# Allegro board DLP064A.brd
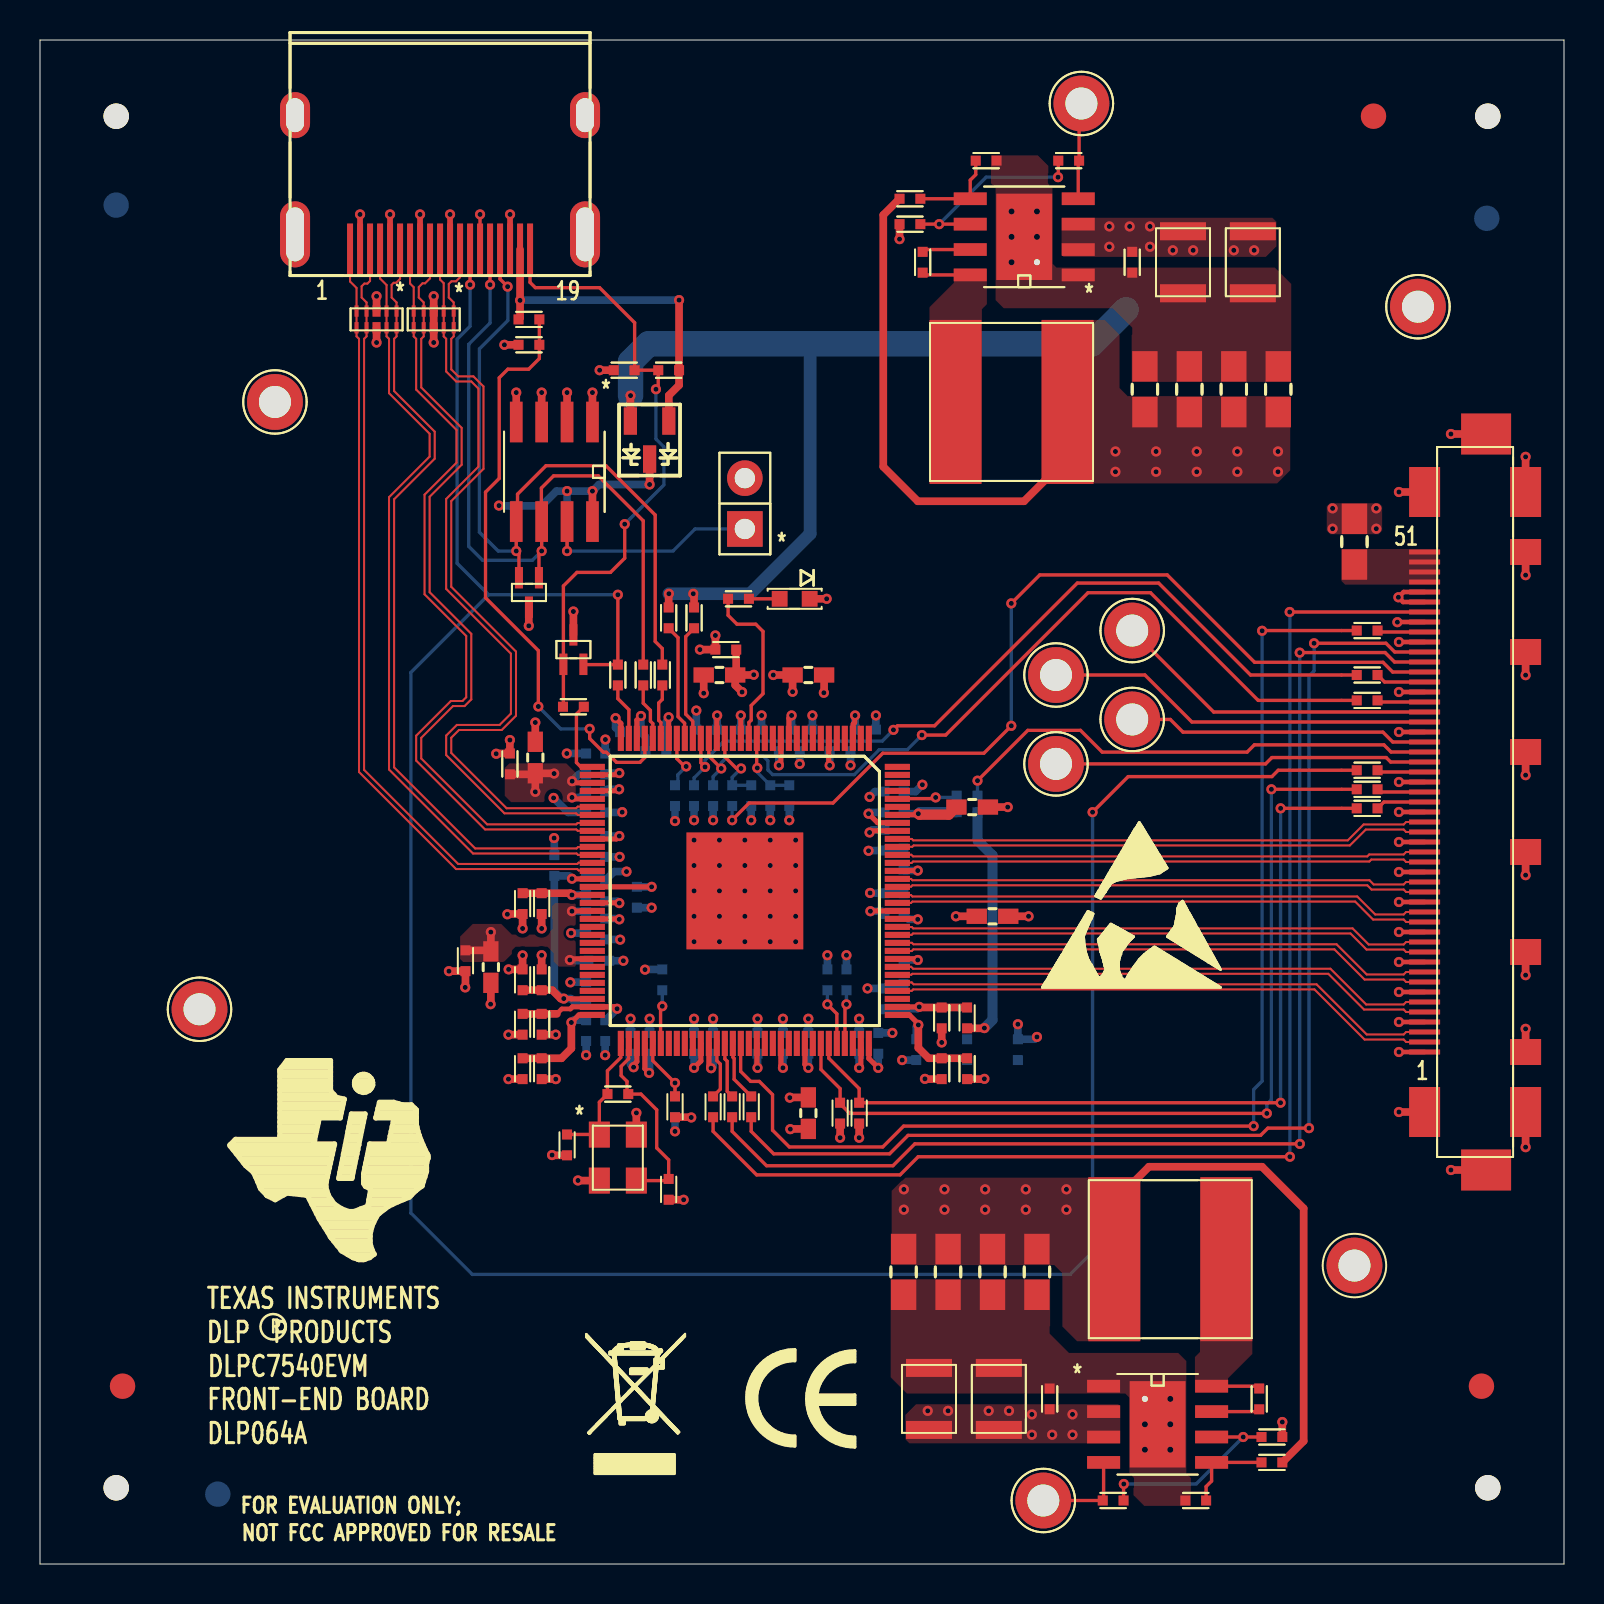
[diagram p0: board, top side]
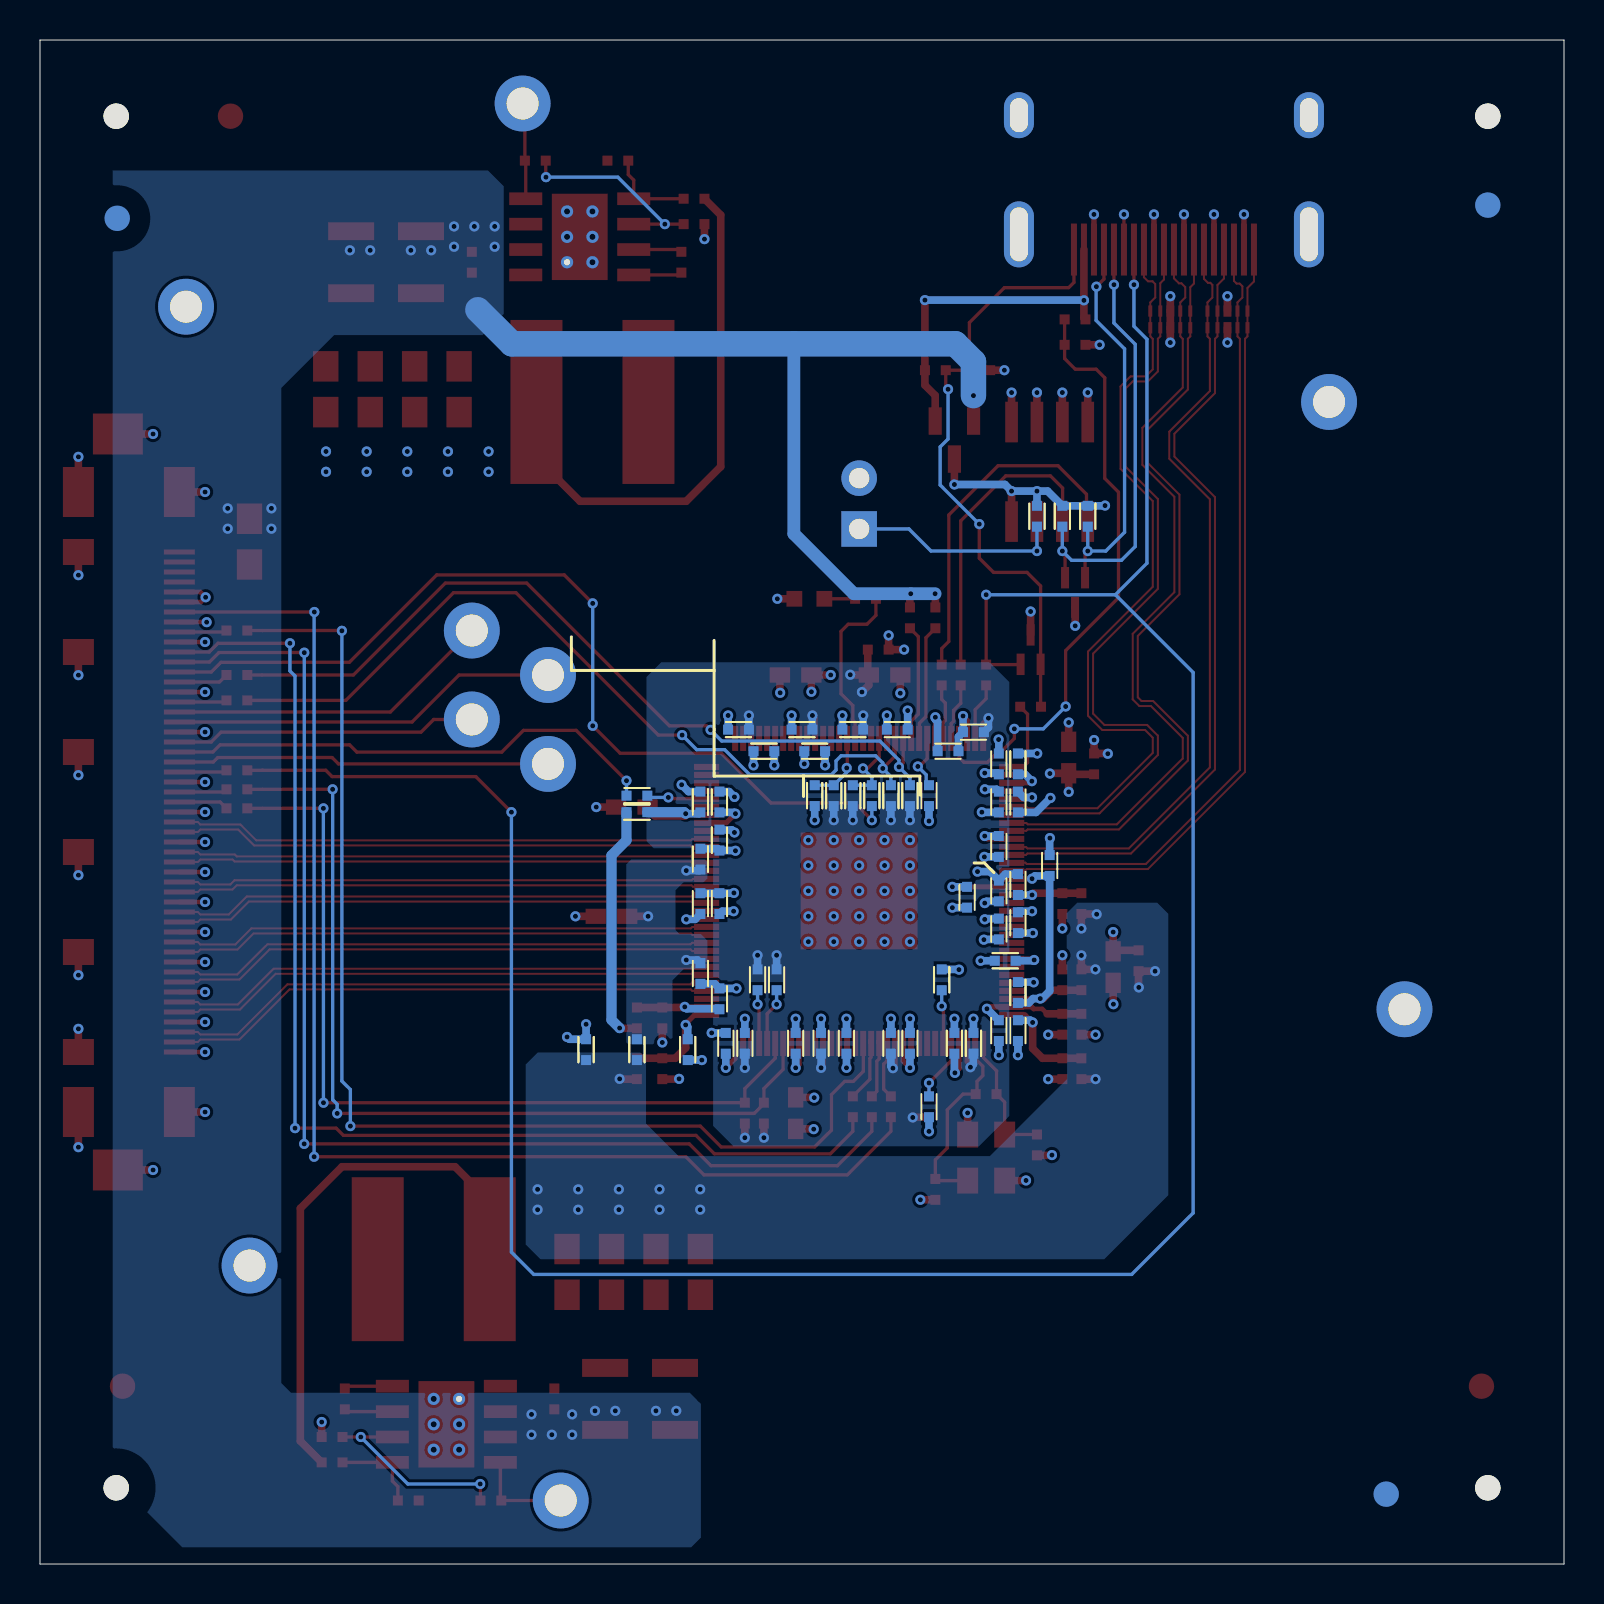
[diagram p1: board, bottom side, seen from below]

Outline 76.2 x 76.2 mm; copper layers: TOP, LY2, LY3, BOTTOM. Coordinates in mm from the lower left corner of the outline.
Outline path: 0,76.2 0,0 76.2,0 76.2,76.2 0,76.2

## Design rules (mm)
constraint set DEFAULT: min track width 0.165
net group TX: nets TX0N TX0P TX1N TX1P TX2N TX2P TX3N TX3P TX4N TX4P TX5N TX5P TX6N TX6P TX7N TX7P

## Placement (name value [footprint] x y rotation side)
C1  1uF  [0402]  43.5 66.99 180 top
C2  100nF  [0402]  44.13 65.09 90 top
C3  100pF  [0402]  54.61 65.09 90 top
C4  10uF  [1210]  57.15 65.09 270 top
C5  10uF  [1210]  60.64 65.09 270 top
C6  22uF  [0805]  55.24 58.74 270 top
C7  22uF  [0805]  57.47 58.74 270 top
C8  22uF  [0805]  59.69 58.74 270 top
C9  22uF  [0805]  61.91 58.74 270 top
C10  10uF  [0603]  24.77 40.32 90 top
C11  10uF  [0603]  33.97 44.45 180 top
C12  10uF  [0603]  38.42 44.45 0 top
C13  10uF  [0603]  22.54 29.84 270 top
C14  4.7uF  [0402]  25.08 33.02 270 top
C15  10uF  [0603]  47.62 32.38 0 top
C16  4.7uF  [0402]  25.08 29.21 90 top
C17  1uF  [0402]  25.08 26.99 270 top
C18  1uF  [0402]  25.08 24.77 270 top
C19  10uF  [0603]  38.42 22.54 270 top
C20  4.7uF  [0402]  45.09 27.3 270 top
C21  4.7uF  [0402]  45.09 24.77 270 top
C22  18pF  [0402]  26.35 20.95 90 top
C23  18pF  [0402]  31.43 18.73 90 top
C24  22uF  [0805]  43.18 14.61 90 top
C25  22uF  [0805]  45.4 14.61 90 top
C26  22uF  [0805]  47.62 14.61 90 top
C27  22uF  [0805]  49.85 14.61 90 top
C28  10uF  [1210]  44.45 8.26 90 top
C29  10uF  [1210]  47.94 8.26 90 top
C30  100pF  [0402]  50.48 8.26 270 top
C31  100nF  [0402]  60.96 8.26 270 top
C32  1uF  [0402]  61.59 6.35 0 top
C33  100nF  [0402]  42.23 38.1 90 bottom
C34  100nF  [0402]  43.18 38.1 90 bottom
C35  100nF  [0402]  41.27 41.72 0 bottom
C36  100nF  [0402]  40.01 40.64 0 bottom
C37  100nF  [0402]  38.1 41.72 0 bottom
C38  100nF  [0402]  37.47 40.64 0 bottom
C39  1uF  [0402]  37.47 38.42 90 bottom
C40  100nF  [0402]  35.56 41.72 0 bottom
C41  100nF  [0402]  33.34 41.72 180 bottom
C42  100nF  [0402]  30.8 40.64 180 bottom
C43  100nF  [0402]  29.53 41.59 0 bottom
C44  100nF  [0402]  28.26 40.01 90 bottom
C45  100nF  [0402]  28.26 38.1 270 bottom
C46  100nF  [0402]  27.3 40.01 90 bottom
C47  100nF  [0402]  27.3 38.1 270 bottom
C48  100nF  [0402]  43.18 35.24 90 bottom
C49  100nF  [0402]  43.18 33.02 90 bottom
C50  100nF  [0402]  42.23 36.2 270 bottom
C51  100nF  [0402]  42.23 33.02 90 bottom
C52  100nF  [0402]  29.84 33.34 270 bottom
C53  100nF  [0402]  28.26 35.88 270 bottom
C54  100nF  [0402]  28.26 33.66 90 bottom
C55  100nF  [0402]  28.26 31.75 270 bottom
C56  100nF  [0402]  27.3 33.97 90 bottom
C57  100nF  [0402]  27.3 32.07 270 bottom
C58  100nF  [0402]  25.72 34.92 90 bottom
C59  100nF  [0402]  43.18 29.53 270 bottom
C60  100nF  [0402]  42.23 28.26 90 bottom
C61  100nF  [0402]  28.26 26.67 270 bottom
C62  100nF  [0402]  27.94 30.16 0 bottom
C63  100nF  [0402]  27.3 28.57 90 bottom
C64  100nF  [0402]  27.3 26.67 270 bottom
C65  100nF  [0402]  43.81 25.72 270 bottom
C66  100nF  [0402]  41.91 26.04 90 bottom
C67  100nF  [0402]  40.96 26.04 90 bottom
C68  100nF  [0402]  38.42 26.04 90 bottom
C69  100nF  [0402]  37.15 26.04 90 bottom
C70  100nF  [0402]  35.88 26.04 90 bottom
C71  100nF  [0402]  33.66 26.04 90 bottom
C72  100nF  [0402]  32.7 26.04 90 bottom
C73  100nF  [0402]  30.48 26.04 90 bottom
C74  100nF  [0402]  29.53 26.04 90 bottom
C75  10uF  [0603]  46.61 37.85 0 top
D1  BAT54CFILM  [SOT-23-BAT54S_ST]  30.48 56.2 180 top
D2  RCLAMP0502BATCT  [SEMTECH_SC-75_SOT523]  24.45 48.58 0 top
D3  RCLAMP0502BATCT  [SEMTECH_SC-75_SOT523]  26.67 45.72 180 top
D4  blue  [LED-LTST-C190_LITEON]  37.78 48.26 180 top
J1  2086581001  [MOLEX_47151-0001]  20 65.72 180 top
J2  HDR,2P,1R  [HDR2P_1R]  35.24 51.75 0 top
J3  FI-RE51S-VF-R1300  [FI-R51-HF_VF_DUAL]  71.75 38.1 90 top
L1  6.8uH  [BOURNS_SRN8040]  48.58 58.1 180 top
L2  BLM15PX121SN1D  [0402]  34.29 45.72 180 top
L3  BLM15PX121SN1D  [0402]  23.5 40.01 270 top
L4  BLM15PX121SN1D  [0402]  21.27 30.16 90 top
L5  BLM15PX121SN1D  [0402]  24.13 33.02 90 top
L6  BLM15PX121SN1D  [0402]  24.13 29.21 270 top
L7  BLM15PX121SN1D  [0402]  24.13 26.99 90 top
L8  BLM15PX121SN1D  [0402]  24.13 24.77 90 top
L9  BLM15PX121SN1D  [0402]  46.35 27.3 270 top
L10  BLM15PX121SN1D  [0402]  46.35 24.77 270 top
L11  3.6uH  [BOURNS_SRN8040]  56.52 15.24 0 top
L12  BLM15PX121SN1D  [0402]  48.9 25.72 90 bottom
L13  BLM15PX121SN1D  [0402]  46.35 25.72 270 bottom
L14  BLM15PX121SN1D  [0402]  46.35 37.59 0 bottom
NOREF  -  []  -19.94 -62.8 0 top
NOREF#2  -  []  -68.53 58.93 0 top
NOREF#3  -  []  0 76.2 0 top
NOREF#4  -  []  -10.16 -10.16 0 top
NOREF#5  -  [unnamed#2]  72.39 3.81 90 top
NOREF#6  -  [unnamed#2]  66.67 72.39 90 top
NOREF#7  -  []  0 0 0 top
NOREF#8  -  []  -10.16 86.36 0 top
NOREF#9  -  []  -50.44 43.56 0 top
NOREF#10  -  []  -88.27 72.95 0 top
NOREF#11  -  [unnamed#2]  3.81 3.81 90 top
NOREF#12  -  []  240.78 -103.99 0 top
NOREF#13  -  []  -67.57 -40.82 0 top
NOREF#14  -  []  86.36 86.36 0 top
NOREF#15  -  []  21.03 2.51 0 top
NOREF#16  -  []  0 0 90 top
NOREF#17  -  [unnamed#2]  72.07 8.89 90 top
NOREF#18  -  []  0 0 90 top
NOREF#19  -  [unnamed#2]  3.81 72.39 90 top
NOREF#20  -  [unnamed#2]  4.13 8.89 90 top
NOREF#21  -  [unnamed#2]  72.39 72.39 90 top
NOREF#22  -  []  -25.35 67.44 0 top
NOREF#23  -  [unnamed#2]  8.89 3.49 90 bottom
NOREF#24  -  [unnamed#2]  72.34 67.28 90 bottom
NOREF#25  -  [unnamed#2]  3.81 67.94 90 bottom
R1  100k  [0402]  43.5 68.26 180 top
R2  43.2K  [0402]  47.31 70.17 180 top
R3  100k  [0402]  51.44 70.17 0 top
R4  1.5k  [0402]  24.45 62.23 180 top
R5  3k  [0402]  24.45 60.96 0 top
R6  100k  [0402]  29.21 59.69 0 top
R7  100k  [0402]  31.43 59.69 180 top
R8  10k  [0402]  31.43 47.31 270 top
R9  10k  [0402]  32.7 47.31 270 top
R10  300  [0402]  34.92 48.26 180 top
R11  0  [0805]  65.72 51.12 90 top
R12  22  [0402]  66.36 46.67 180 top
R13  22  [0402]  26.67 42.86 180 top
R14  0  [0402]  28.89 44.45 90 top
R15  22  [0402]  30.16 44.45 90 top
R16  22  [0402]  31.11 44.45 90 top
R17  22  [0402]  66.36 44.45 180 top
R18  22  [0402]  66.36 43.18 180 top
R19  22  [0402]  66.36 39.69 180 top
R20  22  [0402]  66.36 38.73 180 top
R21  22  [0402]  66.36 37.78 180 top
R22  1M  [0402]  28.89 23.5 180 top
R23  10k  [0402]  31.75 22.86 90 top
R24  22  [0402]  33.66 22.86 90 top
R25  22  [0402]  34.61 22.86 90 top
R26  22  [0402]  35.56 22.86 90 top
R27  10k  [0402]  40.01 22.54 90 top
R28  10k  [0402]  40.96 22.54 90 top
R29  100k  [0402]  53.66 3.17 180 top
R30  43.2K  [0402]  57.78 3.17 0 top
R31  0  [0402]  61.59 5.08 0 top
R32  10k  [0402]  26.35 52.39 270 bottom
R33  10k  [0402]  25.08 52.39 270 bottom
R34  10k  [0402]  23.81 52.39 270 bottom
R35  22  [0402]  46.35 38.42 180 bottom
R36  22k  [0402]  36.51 38.42 90 bottom
R37  10k  [0402]  35.56 38.42 90 bottom
R38  22  [0402]  34.61 38.42 90 bottom
R39  10k  [0402]  33.66 38.42 90 bottom
R40  10k  [0402]  32.7 38.42 90 bottom
R41  3k  [0402]  31.75 38.42 270 bottom
R42  10k  [0402]  40.32 29.21 270 bottom
R43  10k  [0402]  39.37 29.21 270 bottom
R44  1k  [0402]  31.11 29.21 270 bottom
R45  10k  [0402]  31.75 22.86 90 bottom
TP1  TP_WHT  [TP_KEYSTONE_5011]  52.07 73.03 180 top
TP2  TP_BLK  [TP_KEYSTONE_5011]  68.9 62.87 0 top
TP3  TP_BLK  [TP_KEYSTONE_5011]  11.75 58.1 0 top
TP4  TP_WHT  [TP_KEYSTONE_5011]  54.61 46.67 0 top
TP5  TP_WHT  [TP_KEYSTONE_5011]  50.8 44.45 0 top
TP6  TP_WHT  [TP_KEYSTONE_5011]  50.8 40.01 0 top
TP7  TP_WHT  [TP_KEYSTONE_5011]  54.61 42.23 0 top
TP8  TP_BLK  [TP_KEYSTONE_5011]  65.72 14.92 0 top
TP9  TP_BLK  [TP_KEYSTONE_5011]  7.98 27.74 0 top
TP10  TP_WHT  [TP_KEYSTONE_5011]  50.16 3.17 0 top
U1  TPD4E05U06DQAR  [TPD4E05U06DQAR_USON10]  16.83 62.23 270 top
U2  TPD4E05U06DQAR  [TPD4E05U06DQAR_USON10]  19.68 62.23 270 top
U3  LMR33620ADDAR  [HSOIC8_DDA0008J]  49.21 66.36 90 top
U4  M24C02-WMN6TP  [SOIC-8_3P90MM_WIDE]  25.72 54.61 180 top
U5  ITE6807  [ITE6807_LQFP128]  35.24 33.66 180 top
U6  LMR33620ADDAR  [HSOIC8_DDA0008J]  55.88 6.99 270 top
Y1  27.000MHz  [ABRACON_ABM8]  28.89 20.32 270 top

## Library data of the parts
C1-C3 C14 C16-C18 C20-C23 C30-C74 = PAS,CAP,NP: alternate symbols: (0402_1mm)
C4-C13 C15 C19 C24-C29 C75 = PAS,CAP,NP
D1 = PAS,DIODE,SCHOTTKY,BAT54CFILM
D2 D3 = PAS,DIODE,TVS,RClamp502b,small
D4 = PAS,DIODE,LED,ALT
J1 = EM,CONN,HDMI,1R,x1
J2 = EM,JMP,2P,1R
J3 = TMP_094452
L1 L11 = PAS,INDUCTOR, large
L2-L10 L12-L14 = PAS,INDUCTOR: alternate symbols: (0402_1mm)
R1-R10 R12-R45 = PAS,R,large: alternate symbols: (0402_1mm)
R11 = PAS,R,large
TP1 TP10 = Testpoint
TP2-TP9 = EM,TERM,TESTPOINT
U1 U2 = PAS,DIODE,ARRAY,TVS,TPD4E05U06
U3 U6 = PWR,REG,LMR33630,HSOIC8,1x
U4 = MEM,EEPROM,24LCxx
U5 = INF,VIDEO,IT6807_LQFP-128_0
Y1 = PAS,CRYSTAL,ABM11

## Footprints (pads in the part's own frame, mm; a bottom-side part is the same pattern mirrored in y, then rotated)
0402
  rect 0.5x0.5 smd: 1(-0.521,0) 2(0.521,0)
0603
  rect 1.016x0.762 smd: 1(-0.787,0) 2(0.787,0)
0805
  rect 1.524x1.27 smd: 1(-1.143,0) 2(1.143,0)
1210
  rect 0.9x2.3 smd: 1(-1.55,0) 2(1.55,0)
ABRACON_ABM8
  rect 1.3x1.05 smd: 1(-1.15,-0.925) 2(1.15,-0.925) 3(1.15,0.925) 4(-1.15,0.925)
BOURNS_SRN8040
  rect 2.6x8.2 smd: 1(-2.8,0) 2(2.8,0)
FI-R51-HF_VF_DUAL
  rect 0.25x1.55 smd: 1(-12.5,2.525) 2(-12,2.525) 3(-11.5,2.525) 4(-11,2.525) 5(-10.5,2.525) 6(-10,2.525) 7(-9.5,2.525) 8(-9,2.525) 9(-8.5,2.525) 10(-8,2.525) 11(-7.5,2.525) 12(-7,2.525) 13(-6.5,2.525) 14(-6,2.525) 15(-5.5,2.525) 16(-5,2.525) 17(-4.5,2.525) 18(-4,2.525) 19(-3.5,2.525) 20(-3,2.525) 21(-2.5,2.525) 22(-2,2.525) 23(-1.5,2.525) 24(-1,2.525) 25(-0.5,2.525) 26(0,2.525) 27(0.5,2.525) 28(1,2.525) 29(1.5,2.525) 30(2,2.525) 31(2.5,2.525) 32(3,2.525) 33(3.5,2.525) 34(4,2.525) 35(4.5,2.525) 36(5,2.525) 37(5.5,2.525) 38(6,2.525) 39(6.5,2.525) 40(7,2.525) 41(7.5,2.525) 42(8,2.525) 43(8.5,2.525) 44(9,2.525) 45(9.5,2.525) 46(10,2.525) 47(10.5,2.525) 48(11,2.525) 49(11.5,2.525) 50(12,2.525) 51(12.5,2.525)
  rect 2.5x1.55 smd: 52(-15.5,2.525) 53(15.5,2.525) 54(-15.5,-2.525) 55(15.5,-2.525)
  rect 1.3x1.55 smd: 56(-12.5,-2.525) 57(-7.5,-2.525) 58(-2.5,-2.525) 59(2.5,-2.525) 60(7.5,-2.525) 61(12.5,-2.525)
  rect 2.05x2.5 smd: 62(18.4,-0.55) 63(-18.4,-0.55)
HDR2P_1R
  rect 1.778x1.778 hole 1.016: 1(0,0)
  round 1.778 hole 1.016: 2(0,2.54)
HSOIC8_DDA0008J
  rect 0.635x1.651 smd: 1(-1.905,-2.7) 2(-0.635,-2.7) 3(0.635,-2.7) 4(1.905,-2.7) 5(1.905,2.7) 6(0.635,2.7) 7(-0.635,2.7) 8(-1.905,2.7)
  round 0.61 hole 0.305: 9(-1.27,-0.635)
ITE6807_LQFP128
  rect 0.305x1.257 smd: 1(-6.2,-7.626) 2(-5.8,-7.626) 3(-5.4,-7.626) 4(-5,-7.626) 5(-4.6,-7.626) 6(-4.2,-7.626) 7(-3.8,-7.626) 8(-3.4,-7.626) 9(-3,-7.626) 10(-2.6,-7.626) 11(-2.2,-7.626) 12(-1.8,-7.626) 13(-1.4,-7.626) 14(-1,-7.626) 15(-0.6,-7.626) 16(-0.2,-7.626) 17(0.2,-7.626) 18(0.6,-7.626) 19(1,-7.626) 20(1.4,-7.626) 21(1.8,-7.626) 22(2.2,-7.626) 23(2.6,-7.626) 24(3,-7.626) 25(3.4,-7.626) 26(3.8,-7.626) 27(4.2,-7.626) 28(4.6,-7.626) 29(5,-7.626) 30(5.4,-7.626) 31(5.8,-7.626) 32(6.2,-7.626) 65(6.2,7.626) 66(5.8,7.626) 67(5.4,7.626) 68(5,7.626) 69(4.6,7.626) 70(4.2,7.626) 71(3.8,7.626) 72(3.4,7.626) 73(3,7.626) 74(2.6,7.626) 75(2.2,7.626) 76(1.8,7.626) 77(1.4,7.626) 78(1,7.626) 79(0.6,7.626) 80(0.2,7.626) 81(-0.2,7.626) 82(-0.6,7.626) 83(-1,7.626) 84(-1.4,7.626) 85(-1.8,7.626) 86(-2.2,7.626) 87(-2.6,7.626) 88(-3,7.626) 89(-3.4,7.626) 90(-3.8,7.626) 91(-4.2,7.626) 92(-4.6,7.626) 93(-5,7.626) 94(-5.4,7.626) 95(-5.8,7.626) 96(-6.2,7.626)
  rect 1.257x0.305 smd: 33(7.626,-6.2) 34(7.626,-5.8) 35(7.626,-5.4) 36(7.626,-5) 37(7.626,-4.6) 38(7.626,-4.2) 39(7.626,-3.8) 40(7.626,-3.4) 41(7.626,-3) 42(7.626,-2.6) 43(7.626,-2.2) 44(7.626,-1.8) 45(7.626,-1.4) 46(7.626,-1) 47(7.626,-0.6) 48(7.626,-0.2) 49(7.626,0.2) 50(7.626,0.6) 51(7.626,1) 52(7.626,1.4) 53(7.626,1.8) 54(7.626,2.2) 55(7.626,2.6) 56(7.626,3) 57(7.626,3.4) 58(7.626,3.8) 59(7.626,4.2) 60(7.626,4.6) 61(7.626,5) 62(7.626,5.4) 63(7.626,5.8) 64(7.626,6.2) 97(-7.626,6.2) 98(-7.626,5.8) 99(-7.626,5.4) 100(-7.626,5) 101(-7.626,4.6) 102(-7.626,4.2) 103(-7.626,3.8) 104(-7.626,3.4) 105(-7.626,3) 106(-7.626,2.6) 107(-7.626,2.2) 108(-7.626,1.8) 109(-7.626,1.4) 110(-7.626,1) 111(-7.626,0.6) 112(-7.626,0.2) 113(-7.626,-0.2) 114(-7.626,-0.6) 115(-7.626,-1) 116(-7.626,-1.4) 117(-7.626,-1.8) 118(-7.626,-2.2) 119(-7.626,-2.6) 120(-7.626,-3) 121(-7.626,-3.4) 122(-7.626,-3.8) 123(-7.626,-4.2) 124(-7.626,-4.6) 125(-7.626,-5) 126(-7.626,-5.4) 127(-7.626,-5.8) 128(-7.626,-6.2)
  rect 5.842x5.842 smd: 129(0,0)
LED-LTST-C190_LITEON
  rect 0.787x0.787 smd: 1(-0.7,0) 2(0.8,0)
MOLEX_47151-0001
  rect 0.3x2.6 smd: 1(4.5,0) 2(4,0) 3(3.5,0) 4(3,0) 5(2.5,0) 6(2,0) 7(1.5,0) 8(1,0) 9(0.5,0) 10(0,0) 11(-0.5,0) 12(-1,0) 13(-1.5,0) 14(-2,0) 15(-2.5,0) 16(-3,0) 17(-3.5,0) 18(-4,0) 19(-4.5,0)
  oval 1.5x3.3 hole 0.9x2.7: 20(-7.25,-0.76) 21(7.25,-0.76)
  oval 1.5x2.3 hole 0.9x1.7: 22(-7.25,-6.72) 23(7.25,-6.72)
SEMTECH_SC-75_SOT523
  rect 0.4x1.07 smd: 1(-0.5,0.737) 2(0.5,0.737) 3(0,-0.737)
SOIC-8_3P90MM_WIDE
  rect 0.635x2.032 smd: 1(-1.905,-2.489) 2(-0.635,-2.489) 3(0.635,-2.489) 4(1.905,-2.489) 5(1.905,2.489) 6(0.635,2.489) 7(-0.635,2.489) 8(-1.905,2.489)
SOT-23-BAT54S_ST
  rect 0.66x1.372 smd: 1(-0.96,-0.95) 2(0.96,-0.95) 3(0,0.95)
TP_KEYSTONE_5011
  round 2.794 hole 1.6: 1(0,0)
TPD4E05U06DQAR_USON10
  rect 0.565x0.2 smd: 1(-0.418,1) 2(-0.418,0.5) 4(-0.418,-0.5) 5(-0.418,-1) 6(0.418,-1) 7(0.418,-0.5) 9(0.418,0.5) 10(0.418,1)
  rect 0.565x0.4 smd: 3(-0.418,0) 8(0.418,0)
unnamed#2
  round 1.27 hole 3.429 unplated: (0,0)

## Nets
AVDD10: C13.1 C45.1 C53.1 C57.1 C62.1 L4.2 U5.36 U5.42 U5.51 U5.57
DVDD10: C16.1 C58.1 C63.1 L6.2 U5.47 U5.62
GND: C1.2 C3.1 C4.2 C5.2 C6.1 C7.1 C8.1 C9.1 C10.2 C11.2 C12.2 C13.2 C14.2 C15.2 C16.2 C17.2 C18.2 C19.2 C20.2 C21.2 C22.1 C23.1 C24.1 C25.1 C26.1 C27.1 C28.2 C29.2 C30.1 C32.2 C33.2 C34.2 C35.2 C36.2 C37.2 C38.2 C39.1 C40.2 C41.2 C42.2 C43.2 C44.2 C45.2 C46.2 C47.2 C48.2 C49.2 C50.2 C51.2 C52.2 C53.2 C54.2 C55.2 C56.2 C57.2 C58.2 C59.2 C60.2 C61.2 C62.2 C63.2 C64.2 C65.2 C66.2 C67.2 C68.2 C69.2 C70.2 C71.2 C72.2 C73.2 C74.2 C75.2 D2.3 D3.3 D4.1(CATHODE) J1.2 J1.5 J1.8 J1.11 J1.17 J1.20 J1.21 J1.22 J1.23 J2.2 J3.1 J3.4 J3.7 J3.10 J3.13 J3.16 J3.19 J3.22 J3.25 J3.28 J3.33 J3.37 J3.42 J3.44 J3.46 J3.47 J3.52 J3.53 J3.54 J3.55 J3.56 J3.57 J3.58 J3.59 J3.60 J3.61 J3.62 J3.63(GND#63) R2.1 R5.1 R6.1 R30.1 R41.2(N2) R44.1 R45.1 TP2.1(P1) TP3.1(P1) TP8.1(P1) TP9.1(P1) U1.3 U1.8 U2.3 U2.8 U3.1 U3.9 U4.1 U4.2 U4.3 U4.4 U5.30 U5.129 U6.1 U6.9 Y1.2 Y1.4
P5V: J3.48 J3.49 J3.50 J3.51 R11.1
P5V_HDMI0: D1.3 R32.1 R33.1 R34.1 U4.8
PVCC10: C14.1 C44.1 C56.1 L5.2 U5.34 U5.49
VCC33: C10.1 C46.1 C47.1 C54.1 C55.1 L3.2 U5.35 U5.37 U5.50 U5.52
A_HTPDN: R20.2(N2) R27.2(N2) U5.90
A_LOCKN: R21.2(N2) R28.2(N2) U5.91
APVCC10: C18.1 C64.1 L8.2 U5.64
APVCC33: C17.1 C61.1 L7.2 U5.63
B_HTPDN: R43.2(N2) U5.92
B_LOCKN: R42.2(N2) U5.93
CBUS_HPD: R13.1 U5.33
CEC: R14.1 U5.31
DDCSCL0: R15.1 U5.28
DDCSCL1: R8.2(N2) U5.24
DDCSDA0: R16.1 U5.27
DDCSDA1: R9.2(N2) U5.23
EDID_WP: J2.1 R32.2(N2) U4.7(WP)
ENTEST: R44.2(N2) U5.70
FE_3D_LR: J3.31 R35.1
HDMI_0_VCC5: D1.1 J1.18 R4.2(N2) R7.1
HDMI_CEC: J3.29 R19.1
HTPDN: J3.27 R20.1
I2C_BUSY: J3.35 TP4.1(P1)
IIC0_SCL: J3.34 TP5.1(P1)
IIC0_SDA: J3.32 TP7.1(P1)
IIC1_SCL: J3.38 R17.1
IIC1_SDA: J3.36 R18.1
INT#_SCDT: R37.2(N2) R38.2(N2) U5.19
IVDD10: C12.1 C19.1 C33.1 C36.1 C38.1 C41.1 C42.1 C51.1 C52.1 C66.1 C68.1 C70.1 C72.1 C73.1 L12.2 U5.6 U5.12 U5.20 U5.26 U5.48 U5.68 U5.75 U5.82 U5.88 U5.96 U5.110 U5.121
LOCKN: J3.26 R21.1
OVDD33: C11.1 C35.1 C37.1 C40.1 C43.1 C67.1 C69.1 C71.1 C74.1 L2.1 R23.1 R27.1 R28.1 R36.1 R37.1 R39.1 R40.1 R42.1 R43.1 U5.3 U5.11 U5.17 U5.32 U5.67 U5.76 U5.85 U5.95
P0_RX0N: J1.9 U2.4 U2.7 U5.40
P0_RX0P: J1.7 U2.5 U2.6 U5.41
P0_RX1N: J1.6 U1.1 U1.10(NC4) U5.43
P0_RX1P: J1.4 U1.2 U1.9 U5.44
P0_RX2N: J1.3 U1.4 U1.7 U5.45
P0_RX2P: J1.1 U1.5 U1.6 U5.46
P0_RXCN: J1.12 U2.1 U2.10(NC4) U5.38
P0_RXCP: J1.10 U2.2 U2.9 U5.39
P1P0V: C24.2 C25.2 C26.2 C27.2 L4.1 L5.1 L6.1 L8.1 L10.2 L11.1 L12.1 L13.2 R31.2(N2)
P1P0V_BOOT: C31.2 U6.7
P1P0V_FB: R30.2(N2) R31.1 U6.5
P1P0V_PWRGOOD: R29.2(N2) TP10.1 U6.4
P1P0V_SW: C31.1 L11.2 U6.8
P1P0V_VCC: C32.1 R29.1 U6.6
P3P3V: C6.2 C7.2 C8.2 C9.2 L1.1 L2.2 L3.1 L7.1 L9.2 L14.2 R1.2(N2)
P3P3V_BOOT: C2.2 U3.7
P3P3V_FB: R1.1 R2.2(N2) U3.5
P3P3V_PWRGOOD: R3.2(N2) TP1.1 U3.4
P3P3V_SW: C2.1 L1.2 U3.8
P3P3V_VCC: C1.1 R3.1 U3.6
P5P0V: C3.2 C4.1 C5.1 C28.1 C29.1 C30.2 D1.2 R8.1 R9.1 R11.2(N2) U3.2(VIN) U3.3 U6.2(VIN) U6.3
PCADR: R23.2(N2) R45.2(N2) U5.69
PCSCL: R17.2(N2) R40.2(N2) U5.22
PCSDA: R18.2(N2) R39.2(N2) U5.21
R0PWR5V: R4.1 R5.2(N2) U5.29
R1PWR5V: R41.1 U5.25
RX_CEC: D3.1 J1.13 R14.2(N2) R19.2(N2)
RX_HPD0: D3.2 J1.19 R6.2(N2) R7.2(N2) R13.2(N2)
SATUS_INT: J3.39 R38.1
SCDT_3DR_EVODD: R35.2(N2) U5.124
SCDT_DR5: R10.2(N2) U5.16
SCDT_DR5_LED: D4.2 R10.1
SCL_HDMI0_DDC_CI: D2.2 J1.15 R15.2(N2) R33.2(N2) U4.6
SDA_HDMI0_DDC_CI: D2.1 J1.16 R16.2(N2) R34.2(N2) U4.5
SPI1_CLK: J3.45 R24.1
SPI1_CSZ_X: J3.40 R25.1
SPI1_SIMO: J3.41 R26.1
SPI1_SOMI: J3.43 R12.1
SPI_CLK: R24.2(N2) U5.77
SPI_DI: R12.2(N2) U5.80
SPI_DO: R26.2(N2) U5.79
SPI_SS: R25.2(N2) U5.78
SYSRSTN: C39.2 R36.2(N2) U5.15
TVCC33: C34.1 C75.1 L14.1 U5.122
TX0N: J3.24 U5.119
TX0P: J3.23 U5.118
TX1N: J3.21 U5.117
TX1P: J3.20 U5.116
TX2N: J3.18 U5.114
TX2P: J3.17 U5.113
TX3N: J3.15 U5.112
TX3P: J3.14 U5.111
TX4N: J3.12 U5.108
TX4P: J3.11 U5.107
TX5N: J3.9 U5.106
TX5P: J3.8 U5.105
TX6N: J3.6 U5.103
TX6P: J3.5 U5.102
TX7N: J3.3 U5.101
TX7P: J3.2 U5.100
VBO_AVDD10: C15.1 C48.1 C59.1 L13.1 U5.104 U5.115
VBO_PVCC10: C21.1 C49.1 C50.1 C65.1 L10.1 U5.97 U5.109 U5.120
VBO_PVCC33: C20.1 C60.1 L9.1 U5.98
VX1_PROJ_ON: J3.30 TP6.1(P1)
XTALIN: C23.2 R22.1 U5.66 Y1.3
XTALOUT: C22.2 R22.2(N2) U5.65(XTALOUT) Y1.1

Pads without a net: J1 14; U5 1 2 4 5 7 8 9 10 13 14 18 53 54 55 56 58 59 60 61 71 72 73 74 81 83 84 86 87 89 94 99 123 125 126 127 128

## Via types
v1: diameter 0.508, hole 0.254, TOP to BOTTOM, 300 vias
v2: diameter 0.61, hole 0.305, TOP to BOTTOM, 10 vias

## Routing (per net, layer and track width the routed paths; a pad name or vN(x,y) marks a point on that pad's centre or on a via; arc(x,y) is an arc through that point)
AVDD10: length 10.6
  TOP w0.127: U5.51 27.62,32.65
  TOP w0.254: U5.42 27.78,36.25 27.79,36.25 28.82,36.25 v1(28.96,36.4) ; v1(28.96,38.73) 28.88,38.66 27.83,38.66 27.82,38.65 U5.36 ; v1(26.49,30.2) 26.55,30.26 27.74,30.26 27.74,30.25 U5.57 ; v1(26.6,32.64) 26.61,32.65 27.62,32.65
  TOP w0.381: v1(22.54,31.6) C13.1 22.49,30.68 L4.2
  BOTTOM w0.381: v1(28.96,38.73) 28.37,38.73 C45.1 ; v1(26.49,30.2) 26.53,30.16 C62.1 ; C57.1 27.25,32.64 v1(26.6,32.64) ; C53.1 v1(28.96,36.4)
DVDD10: length 13.6
  TOP w0.127: 27.74,34.26 27.74,34.25 U5.47
  TOP w0.254: 27.74,34.26 26.61,34.26 v1(26.6,34.26) ; v1(26.19,28.27) 26.54,28.27 26.56,28.25 U5.62 27.74,28.25
  TOP w0.381: L6.2 C16.1 25.62,28.69 26.04,28.27 v1(26.19,28.27)
  BOTTOM w0.381: v1(26.6,34.26) 26.46,34.4 C58.1 25.72,28.65 26.1,28.27 v1(26.19,28.27) 26.54,28.27 26.76,28.05 C63.1
GND: length 235.7
  TOP w0.229: J3.47 68.18,48.6 v1(67.92,48.34) 68.16,48.1 J3.46 ; v1(67.87,47.09) 67.88,47.1 J3.44 ; J3.16 v1(67.95,33.1) ; J3.25 v1(67.95,37.6) ; J3.1 v1(67.95,25.6) ; J3.10 v1(67.95,30.1) ; J3.22 v1(67.95,36.1) ; J3.37 v1(67.95,43.6) ; J3.28 v1(67.95,39.1) ; J3.42 v1(67.95,46.1) ; J3.7 v1(67.95,28.6) ; J3.19 v1(67.95,34.6) ; J3.33 v1(67.95,41.6) ; J3.13 v1(67.95,31.6) ; J3.4 v1(67.95,27.1)
  TOP w0.254: 29.84,41.15 U5.30 29.84,42.19 v1(30.05,42.4)
  TOP w0.279: J1.11 v1(20.5,67.48) ; J1.2 v1(16,67.48) ; J1.17 v1(23.5,67.48) ; J1.5 v1(17.5,67.48) ; J1.8 v1(19,67.48)
  TOP w0.381: U4.3 v1(25.08,58.57) ; C10.2 v1(24.77,42.08) ; v1(26.9,19.18) 26.91,19.17 Y1.2 ; J3.53 v1(67.95,53.6) ; C11.2 v1(33.19,43.54) ; Y1.4 29.82,22.55 v1(29.82,22.56) ; U1.3 v1(16.83,63.39) ; R6.1 v1(27.98,59.69) ; C19.2 37.53,21.76 v1(37.52,21.74) ; R5.1 v1(23.22,60.96) ; v1(19.68,61.07) U2.8 U2.3 v1(19.68,63.39) ; J3.54 v1(74.28,20.84) ; C21.2 44.26,24.24 v1(44.25,24.26) ; J3.58 v1(74.28,34.44) ; v1(24.44,46.91) 24.44,47.83 D2.3 ; v1(39.19,43.56) 39.2,43.57 C12.2 ; C20.2 v1(45.09,26.08) ; C14.2 v1(25.08,31.78) ; C13.2 22.54,28 v1(22.53,27.99) ; C17.2 v1(25.79,26.47) ; J3.63 v1(70.55,19.7) ; C1.2 v1(42.98,66.24) ; C16.2 v1(25.08,30.44) ; J3.52 v1(67.95,22.6) ; J3.59 v1(74.28,39.44) ; U4.4 v1(23.81,58.57) ; J3.62 v1(70.55,56.5) ; J3.56 v1(74.28,26.76) ; J3.61 v1(74.28,49.44) ; C23.1 v1(32.18,18.21) ; J3.60 v1(74.28,44.44) ; D4.1 v1(39.33,48.26) ; C15.2 v1(49.43,32.38) ; U4.1 v1(27.62,58.57) ; v1(16.83,61.07) U1.8 ; J3.57 v1(74.28,29.44) ; U4.2 v1(26.35,58.57) ; C32.2 v1(62.12,7.1) ; C22.1 25.62,20.43 v1(25.6,20.45) ; J3.55 v1(74.28,55.36) ; C75.2 v1(48.39,37.85) ; C18.2 v1(25.79,24.24) ; D3.3 v1(26.67,47.62)
  LY2 w0.635: 26.32,64.65 J1.20 ; J1.20 26.32,68.31 ; J1.20 28.18,64.65 ; J1.20 28.18,68.31 ; TP2.1 70.06,64.03 ; TP2.1 70.06,61.7 ; TP2.1 67.73,61.7 ; TP2.1 67.73,64.03 ; J2.2 36.05,55.1 ; J2.2 36.05,53.49 ; J2.2 34.44,55.1 ; J2.2 34.44,53.49 ; 26.32,71.11 J1.22 ; J1.22 26.32,73.77 ; J1.22 28.18,71.11 ; J1.22 28.18,73.77 ; 11.82,73.77 J1.23 ; J1.23 13.68,71.11 ; J1.23 11.82,71.11 ; J1.23 13.68,73.77 ; TP9.1 9.14,28.9 ; TP9.1 9.14,26.57 ; TP9.1 6.81,28.9 ; TP9.1 6.81,26.57 ; 11.82,68.31 J1.21 ; J1.21 13.68,68.31 ; J1.21 11.82,64.65 ; J1.21 13.68,64.65 ; TP3.1 12.91,59.27 ; TP3.1 10.58,56.94 ; TP3.1 12.91,56.94 ; TP3.1 10.58,59.27 ; TP8.1 66.89,16.09 ; TP8.1 66.89,13.76 ; TP8.1 64.56,13.76 ; TP8.1 64.56,16.09
  LY3 w0.635: J1.20 28.18,64.65 ; J1.20 28.18,68.31 ; J1.20 26.32,68.31 ; J1.20 26.32,64.65 ; J1.22 28.18,71.11 ; J1.22 28.18,73.77 ; J1.22 26.32,73.77 ; J1.22 26.32,71.11 ; J2.2 36.05,55.1 ; J2.2 34.44,55.1 ; J2.2 34.44,53.49 ; J2.2 36.05,53.49 ; TP3.1 12.91,59.27 ; TP3.1 10.58,59.27 ; TP3.1 10.58,56.94 ; TP3.1 12.91,56.94 ; TP2.1 70.06,64.03 ; TP2.1 67.73,64.03 ; TP2.1 70.06,61.7 ; TP2.1 67.73,61.7 ; 11.82,71.11 J1.23 ; J1.23 13.68,71.11 ; J1.23 11.82,73.77 ; J1.23 13.68,73.77 ; TP8.1 66.89,16.09 ; TP8.1 66.89,13.76 ; TP8.1 64.56,16.09 ; TP8.1 64.56,13.76 ; J1.21 13.68,64.65 ; J1.21 11.82,68.31 ; J1.21 13.68,68.31 ; J1.21 11.82,64.65 ; TP9.1 9.14,26.57 ; TP9.1 6.81,28.9 ; TP9.1 6.81,26.57 ; TP9.1 9.14,28.9
  BOTTOM w0.381: v1(28.27,41.22) 28.26,41.21 C44.2 ; C33.2 41.74,38.62 v1(41.48,38.35) ; v1(25.7,36.3) 25.72,36.28 C58.2 ; C48.2 42.32,35.76 C50.2 41.44,35.67 v1(41.43,35.66) ; C63.2 26.53,29.1 v1(26.52,29.08) ; v1(41.38,28.78) C60.2 42.46,29.01 C59.2 ; C36.2 v1(40.53,39.93) ; C34.2 43.78,38.62 v1(44.12,38.96) ; v1(30.05,42.4) C43.2 30.28,41.36 C42.2 ; C66.2 v1(42.62,26.56) ; C73.2 v1(30.48,27.26) ; C69.2 v1(37.15,27.26) ; R45.1 v1(31.75,21.63) ; C71.2 v1(33.66,27.26) ; C41.2 v1(32.82,42.67) ; C74.2 v1(29.53,27.26) ; R41.2 v1(31.75,37.15) ; C38.2 v1(37.99,40.01) ; v1(30.25,29.72) 30.26,29.73 R44.1 ; v1(41.5,33.55) 41.52,33.54 C51.2 C49.2 ; C40.2 v1(36.08,42.43) ; C45.2 29.1,37.58 v1(29.11,37.59) ; C64.2 v1(27.3,25.44) ; C52.2 v1(30.58,32.82) ; C56.2 27.94,34.49 C54.2 28.7,34.62 v1(29.33,34.62) ; C53.2 v1(28.98,35.36) ; C72.2 v1(32.7,27.26) ; C47.2 26.4,37.58 v1(25.68,38.3) ; C55.2 28.99,31.23 v1(29.01,31.22) ; C57.2 v1(26.56,31.55) ; C70.2 v1(35.88,27.26) ; C65.2 v1(43.11,25.2) ; C46.2 v1(26.34,40.53) ; C35.2 v1(41.8,42.43) ; v1(28.26,25.44) C61.2 ; C62.2 v1(29.17,30.16) ; C39.1 v1(37.47,37.19) ; C37.2 v1(38.62,42.43) ; C68.2 v1(38.42,27.26) ; C67.2 v1(40.96,27.26)
  vias: v1(32.7,36.2) v1(32.7,34.92) v1(32.7,33.66) v1(32.7,32.38) v1(32.7,31.11) v1(33.97,36.2) v1(33.97,34.92) v1(33.97,33.66) v1(33.97,32.38) v1(33.97,31.11) v1(35.24,36.2) v1(35.24,34.92) v1(35.24,33.66) v1(35.24,32.38) v1(35.24,31.11) v1(36.51,36.2) v1(36.51,34.92) v1(36.51,33.66) v1(36.51,32.38) v1(36.51,31.11) v1(37.78,36.2) v1(37.78,34.92) v1(37.78,33.66) v1(37.78,32.38) v1(37.78,31.11) v2(48.58,67.63) v2(48.58,66.36) v2(48.58,65.09) v2(49.85,67.63) v2(49.85,66.36) v2(55.24,6.99) v2(55.24,5.71) v2(56.52,8.26) v2(56.52,6.99) v2(56.52,5.71)
P5V_HDMI0: length 11.5
  TOP w0.381: U4.8 v1(27.62,53.64) ; D1.3 v1(30.48,53.98)
  BOTTOM w0.381: v1(30.48,53.98) 27.95,53.98 v1(27.62,53.64) v1(26.35,53.64) ; v1(26.35,53.64) 25.82,53.64 R33.1 R34.1 22.96,52.91 v1(22.95,52.92) ; v1(26.35,53.64) R32.1
PVCC10: length 19.1
  TOP w0.127: U5.49 27.61,33.45
  TOP w0.254: v1(28.96,39.55) 28.88,39.46 27.62,39.46 U5.34 ; 27.61,33.45 v1(26.6,33.45)
  TOP w0.381: L5.2 C14.1 26.51,33.54 v1(26.6,33.45)
  LY3 w0.381: v1(28.96,39.55) 27.66,39.55 27.33,39.88 26.16,39.88 25.94,40.09 25.4,40.09 24.19,38.88 24.19,34.53 25.27,33.45 v1(26.6,33.45)
  BOTTOM w0.381: v1(28.96,39.55) 28.32,39.55 C44.1 ; C56.1 v1(26.6,33.45)
VCC33: length 18.4
  TOP w0.127: U5.35 27.74,39.06 27.74,39.06 ; U5.37 27.58,38.25 27.57,38.26
  TOP w0.254: v1(26.6,38.33) 26.67,38.26 27.57,38.26 ; 27.74,39.06 26.69,39.06 v1(26.61,39.14) ; v1(28.96,32.23) 28.94,32.26 27.78,32.26 27.78,32.25 U5.52 ; v1(28.96,33.05) 28.95,33.06 27.82,33.06 27.81,33.06 U5.50
  TOP w0.381: v1(25.7,39.52) 25.69,39.54 C10.1 ; C10.1 24.71,39.48 L3.2 ; C10.1 v1(24.77,38.61)
  LY3 w0.635: v1(28.96,32.23) v1(28.96,33.05) 26.6,35.41 v1(26.6,38.33)
  BOTTOM w0.381: C46.1 26.95,39.48 v1(26.61,39.14) ; v1(28.96,32.23) 28.93,32.27 C55.1 ; v1(28.96,33.05) 28.88,33.13 C54.1 ; v1(26.6,38.33) 27.01,38.33 C47.1
A_HTPDN: length 45.5
  TOP w0.165: U5.90 39.04,25.74 39.05,25.73 39.05,24.73 40.01,23.77 R27.2 40.01,23.01 40.49,22.53 v1(61.34,22.53) ; v1(61.57,38.73) R20.2
  BOTTOM w0.165: v1(61.57,38.73) 61.57,38.73 61.57,23.21 61.34,22.99 v1(61.34,22.53)
A_LOCKN: length 43.2
  TOP w0.165: U5.91 39.44,25.9 39.44,25.89 39.44,25.29 40.96,23.77 R28.2 v1(62.03,23.06) ; v1(62.03,37.78) R21.2
  BOTTOM w0.165: v1(62.03,37.78) 62.03,34.14 62.03,34.13 v1(62.03,23.06)
APVCC10: length 5.9
  TOP w0.254: v1(26.57,27.08) 26.95,27.45 27.53,27.45 27.53,27.46 U5.64
  TOP w0.381: L8.2 C18.1 26.07,25.29 26.57,25.78 v1(26.57,27.08)
  BOTTOM w0.381: v1(26.57,27.08) 26.68,27.19 C64.1
APVCC33: length 6.9
  TOP w0.229: 26.52,27.75 26.09,27.75 25.84,27.51
  TOP w0.254: 26.52,27.75 26.62,27.86 28.76,27.86 28.76,27.85 ; 28.76,27.85 v1(28.85,27.76) ; 28.76,27.85 U5.63
  TOP w0.381: L7.2 C17.1 25.84,27.51
  BOTTOM w0.381: C61.1 28.28,27.19 v1(28.85,27.76)
B_HTPDN: length 2.9
  TOP w0.165: U5.92 39.84,27.51 v1(39.37,27.98)
  BOTTOM w0.165: R43.2 v1(39.37,27.98)
B_LOCKN: length 2.7
  TOP w0.165: U5.93 40.24,26.27 40.25,26.28 40.25,27.91 v1(40.32,27.98)
  BOTTOM w0.165: R42.2 v1(40.32,27.98)
CBUS_HPD: length 3.8
  TOP w0.165: R13.1 26.82,42.49 26.82,40.07 27.03,39.86 27.61,39.86 U5.33
CEC: length 2.9
  TOP w0.165: U5.31 29.44,41.41 29.44,41.41 29.44,42.72 28.89,43.27 R14.1
DDCSCL0: length 2.8
  TOP w0.165: R15.1 30.16,43.04 30.52,42.68 30.52,42.14 30.64,42.02 U5.28
DDCSCL1: length 5.8
  TOP w0.165: U5.24 32.24,41.28 32.23,41.29 32.23,42.04 31.9,42.37 31.9,46.32 R8.2
DDCSDA0: length 2.8
  TOP w0.165: R16.1 31.11,43.23 30.93,43.05 30.93,42.18 31.05,42.07 31.05,41.54
  TOP w0.254: U5.27 31.04,41.54 31.05,41.54
DDCSDA1: length 5.8
  TOP w0.165: R9.2 32.28,46.37 32.28,42.49 32.64,42.14 32.64,41.3 32.64,41.29 U5.23
EDID_WP: length 12
  TOP w0.165: U4.7 v1(26.35,50.65)
  BOTTOM w0.165: R32.2 v1(26.35,50.65) 31.65,50.65 32.75,51.75 J2.1
ENTEST: length 2.7
  TOP w0.165: U5.70 31.04,26.33 31.03,26.34 31.03,27.8 v1(31.11,27.89)
  BOTTOM w0.165: v1(31.11,27.89) R44.2
FE_3D_LR: length 24.9
  TOP w0.165: v1(46.88,39.17) 49.39,41.68 52.03,41.68 53.11,40.6 60.36,40.6 60.72,40.96 67.2,40.96 67.55,40.6 J3.31
  BOTTOM w0.165: R35.1 v1(46.88,39.17)
HDMI_0_VCC5: length 17.7
  TOP w0.381: R4.2 24,62.31 v1(24,63.18) J1.18 ; v1(31.95,63.2) R7.1 31.95,58.94 31.44,58.43 D1.1
  BOTTOM w0.381: v1(24,63.18) 24.02,63.2 v1(31.95,63.2)
HDMI_CEC: length 2.4
  TOP w0.165: R19.1 66.97,39.6 J3.29
HTPDN: length 2.4
  TOP w0.165: J3.27 67.01,38.6 R20.1
I2C_BUSY: length 16.3
  TOP w0.165: TP4.1 58.68,42.6 J3.35
IIC0_SCL: length 19.4
  TOP w0.165: J3.34 57.6,42.1 55.24,44.45 TP5.1
IIC0_SDA: length 15.1
  TOP w0.165: J3.32 67.64,41.1 67.14,41.59 57.15,41.59 56.52,42.23 TP7.1
IIC1_SCL: length 2.5
  TOP w0.165: R17.1 67.23,44.1 J3.38
IIC1_SDA: length 2.4
  TOP w0.165: R18.1 66.96,43.1 J3.36
INT#_SCDT: length 3.9
  TOP w0.165: v1(35.05,39.78) 34.82,39.78 34.24,40.36 34.24,41.02 U5.19
  BOTTOM w0.165: R37.2 R38.2 34.61,39.33 v1(35.05,39.78)
IVDD10: length 32.5
  TOP w0.127: U5.48 27.62,33.86
  TOP w0.254: U5.82 35.84,26.01 35.84,26.01 35.84,24.84 v1(35.88,24.81) ; v1(41.52,32.64) 41.54,32.66 42.72,32.66 42.73,32.66 U5.110 ; v1(32.7,24.81) 33.04,25.15 U5.75 ; v1(30.45,24.56) 30.24,24.77 U5.68 ; U5.121 42.87,37.07 41.88,37.07 v1(41.43,37.52) ; v1(36.94,39.93) 37.04,40.03 37.04,41.28 U5.12 ; U5.26 31.44,41.53 31.43,41.54 v1(31.43,42.34) ; U5.20 33.84,41.3 33.84,41.31 33.84,42.41 v1(33.86,42.43) ; v1(41.91,24.81) 41.44,25.27 41.44,25.83 U5.96 ; U5.88 38.24,26.15 38.24,26.16 38.24,24.98 v1(38.42,24.81) ; U5.6 39.44,41.09 39.44,41.08 39.44,39.98 v1(39.48,39.93) ; 27.62,33.86 v1(30.58,33.86)
  TOP w0.381: v1(37.63,43.61) C12.1 v1(36.66,44.45) ; v1(37.49,23.32) 37.5,23.33 C19.1
  BOTTOM w0.381: C66.1 v1(41.91,24.81) ; C70.1 v1(35.88,24.81) ; C73.1 30.48,24.58 v1(30.45,24.56) ; C72.1 v1(32.7,24.81) ; C52.1 v1(30.58,33.86) ; v1(31.43,42.34) 31.43,42.23 31.32,42.11 C42.1 ; v1(41.43,37.52) 41.49,37.58 C33.1 ; C68.1 v1(38.42,24.81) ; C38.1 v1(36.94,39.93) ; v1(48.9,26.99) L12.2 49.73,26.24 v1(49.85,26.35) ; v1(41.52,32.64) 42.09,32.64 C51.1 ; C41.1 v1(33.86,42.43) ; C36.1 v1(39.48,39.93)
LOCKN: length 2.5
  TOP w0.165: R21.1 67.2,38.1 J3.26
Net_84: length 1.8
  TOP w0.165: 22,65.72 v1(22,67.48)
OVDD33: length 25.9
  TOP w0.254: v1(35.04,42.43) 35.04,41.15 35.04,41.16 U5.17 ; v1(29.68,24.84) 29.68,24.96 29.84,25.12 U5.67 29.84,26.16 ; U5.3 40.66,41.3 40.66,42 40.73,42.07 v1(40.75,42.43) ; U5.32 29.04,41.42 29.04,42.03 v1(28.78,42.29) ; v1(37.58,42.43) 37.44,42.29 37.44,41.32 37.44,41.31 U5.11 ; v1(33.55,24.79) 33.44,24.9 U5.76 ; U5.95 41.04,25.82 41.04,25.81 41.04,24.89 v1(40.96,24.81) ; U5.85 37.04,26.15 37.04,26.16 37.04,24.91 v1(37.15,24.81)
  TOP w0.381: C11.1 34.76,43.94 v1(35.1,43.6) ; C11.1 35.67,44.45 v1(35.69,44.46) ; C11.1 34.81,44.5 L2.1 ; R27.1 v1(40.01,21.31) ; R23.1 32.55,22.34 v1(32.56,22.33) ; R28.1 v1(40.96,21.31)
  BOTTOM w0.381: C67.1 v1(40.96,24.81) ; R40.1 v1(32.7,37.19) ; C35.1 v1(40.75,42.43) ; v1(33.55,24.79) 33.66,24.89 C71.1 ; C43.1 28.78,41.82 v1(28.78,42.29) ; C69.1 v1(37.15,24.81) ; R39.1 v1(33.66,37.19) ; R43.1 v1(39.37,30.44) ; C74.1 29.53,24.99 v1(29.68,24.84) ; R37.1 v1(35.56,37.19) ; C40.1 v1(35.04,42.43) ; C37.1 v1(37.58,42.43) ; R36.1 v1(36.51,37.19) ; R42.1 v1(40.32,30.44)
P0_RX0N: length 39.6
  TOP w0.102: U5.40 27.61,37.05 26.88,37.05 26.81,36.98 22.36,36.98 19.06,40.28 19.06,41.31 20.65,42.9 21.23,42.9 21.56,43.23 21.56,46.51 19.48,48.59 19.48,53.36 21.08,54.96 21.08,56.81 19.06,58.83 19.06,61.26 19.18,61.38 U2.7 U2.4 19.18,63.08 18.94,63.32 18.94,63.85 19.13,64.03 19.25,64.03 19.5,64.28 J1.9
  TOP w0.127: U5.40 27.62,37.05
P0_RX0P: length 39.8
  TOP w0.102: J1.7 18.5,64.02 18.69,63.84 U2.5 U2.6 18.69,61.38 18.81,61.26 18.81,58.72 20.83,56.7 20.83,55.07 19.23,53.47 19.23,48.48 21.31,46.4 21.31,43.34 21.12,43.15 20.54,43.15 18.81,41.41 18.81,40.17 22.25,36.73 26.82,36.73 26.89,36.66 27.62,36.66
  TOP w0.127: U5.41 27.62,36.66 27.71,36.66
P0_RX1N: length 39.6
  TOP w0.102: J1.6 18,64.26 17.81,64.06 17.68,64.06 17.58,63.96 17.58,63.32 17.83,63.08 U1.1 U1.10 17.83,61.38 17.7,61.26 17.7,58.65 19.74,56.62 19.74,55.27 17.7,53.24 17.7,39.83 21.76,35.78 26.83,35.78 26.9,35.84 27.53,35.84 27.54,35.85 U5.43
P0_RX1P: length 39.8
  TOP w0.102: J1.4 17,64.27 17.33,63.95 U1.2 U1.9 17.33,61.38 17.45,61.26 17.45,58.54 19.48,56.51 19.48,55.37 17.45,53.34 17.45,39.73 21.65,35.52 26.83,35.52 26.9,35.46 U5.44
P0_RX2N: length 39.8
  TOP w0.102: J1.3 16.5,64.15 16.37,64.02 16.22,64.02 16.08,63.88 16.08,63.32 16.33,63.08 U1.4 U1.7 16.33,61.38 16.2,61.26 16.2,39.71 20.91,35 26.86,35 26.93,35.07 27.55,35.07 27.56,35.06 U5.45
P0_RX2P: length 40
  TOP w0.102: J1.1 15.5,64.13 15.83,63.8 U1.5 U1.6 15.83,61.38 15.95,61.26 15.95,39.6 20.8,34.75 26.86,34.75 26.93,34.68 27.56,34.68 27.59,34.65 U5.46
P0_RXCN: length 39.7
  TOP w0.102: J1.12 21,64.33 20.8,64.14 20.57,64.14 20.44,64 20.44,63.32 20.68,63.08 U2.1 U2.10 20.68,61.38 20.56,61.26 20.56,59.73 20.91,59.38 21.67,59.38 22.17,58.88 22.17,54.76 20.56,53.15 20.56,48.86 23.8,45.62 23.8,42.41 23.09,41.7 20.95,41.7 20.56,41.31 20.56,40.55 23.33,37.79 26.81,37.79 26.89,37.87 27.63,37.87
  TOP w0.127: U5.38 27.63,37.87 27.64,37.86
P0_RXCP: length 39.7
  TOP w0.102: U5.39 27.61,37.45 26.89,37.45 26.81,37.53 23.22,37.53 20.31,40.45 20.31,41.42 20.84,41.95 22.98,41.95 23.55,42.52 23.55,45.52 20.31,48.75 20.31,53.25 21.92,54.86 21.92,58.77 21.56,59.13 20.81,59.13 20.31,59.63 20.31,61.26 20.19,61.38 U2.9 U2.2 20.19,64.04 20,64.22 J1.10
  TOP w0.127: U5.39 27.63,37.46
P1P0V: length 29.4
  TOP w0.381: v1(24.13,30.43) L6.1 v1(23.43,29.73) ; v1(20.45,29.64) L4.1 21.27,28.84 v1(21.26,28.83) ; R31.2 63.18,6.15 63.18,17.78 61.1,19.86 55.45,19.86 54.36,18.77 ; L8.1 v1(23.42,24.24) ; v1(23.37,32.49) 23.38,32.5 L5.1 v1(24.13,31.78) ; v1(47.22,24.26) 47.21,24.24 L10.2
  vias: v1(43.19,18.73) v1(43.19,17.72) v1(45.22,18.73) v1(45.22,17.72) v1(47.26,18.73) v1(47.26,17.72) v1(49.29,18.73) v1(49.29,17.72) v1(51.32,18.73) v1(51.32,17.72)
P1P0V_BOOT: length 2.4
  TOP w0.165: C31.2 60.85,7.62 U6.7
P1P0V_FB: length 4.5
  TOP w0.165: R31.1 U6.5 58.58,4.15 58.31,3.87 R30.2
P1P0V_PWRGOOD: length 4.9
  TOP w0.165: U6.4 53.18,3.22 R29.2 TP10.1
P1P0V_SW: length 2.4
  TOP w0.165: U6.8 60.85,8.89 C31.1
P1P0V_VCC: length 10.3
  TOP w0.165: v1(54.19,4) 54.18,3.99 R29.1 ; C32.1 v1(60.16,6.35) U6.6
  BOTTOM w0.165: v1(54.19,4) 57.81,4 v1(60.16,6.35)
P3P3V: length 40.2
  TOP w0.381: L9.2 47.21,26.78 v1(47.22,26.8) ; v1(23.5,41.2) L3.1 22.82,40.53 v1(22.81,40.51) ; v1(33.77,46.43) L2.2 v1(32.99,45.72) ; 51.31,55.24 49.2,53.14 43.89,53.14 42.16,54.86 42.16,67.45 R1.2 ; L7.1 v1(23.42,26.47)
  BOTTOM w0.508: v1(47.22,26.8) 47.62,27.2 47.62,35.43 46.88,36.18 L14.2
  vias: v1(53.77,55.63) v1(53.77,54.61) v1(55.8,55.63) v1(55.8,54.61) v1(57.84,55.63) v1(57.84,54.61) v1(59.87,55.63) v1(59.87,54.61) v1(61.9,55.63) v1(61.9,54.61)
P3P3V_BOOT: length 2.4
  TOP w0.165: U3.7 44.25,65.72 C2.2
P3P3V_FB: length 4.5
  TOP w0.165: R1.1 U3.5 46.51,69.19 46.79,69.47 R2.2
P3P3V_PWRGOOD: length 4.8
  TOP w0.165: TP1.1 51.96,72.91 R3.2 51.91,70.12 U3.4
P3P3V_SW: length 2.4
  TOP w0.165: U3.8 44.25,64.45 C2.1
P3P3V_VCC: length 10.2
  TOP w0.165: v1(50.9,69.34) 50.91,69.35 R3.1 ; U3.6 v1(44.96,66.99) C1.1
  BOTTOM w0.165: v1(50.9,69.34) 47.31,69.34 v1(44.96,66.99)
P5P0V: length 48
  TOP w0.381: R9.1 32.7,48.48 v1(32.66,48.51) ; v1(31.45,48.51) 31.43,48.5 R8.1 ; D1.2 29.52,58.41 v1(29.53,58.42)
  BOTTOM w0.635: v1(31.45,48.51) v1(32.66,48.51) 35.51,48.51 38.51,51.51 38.51,61.01
  BOTTOM w1.27: v1(29.53,58.42) 29.53,60.11 30.43,61.01 52.6,61.01 54.31,62.71
  vias: v1(44.39,7.66) v1(45.4,7.66) v1(47.43,7.66) v1(48.45,7.66) v1(49.59,7.48) v1(49.59,6.46) v1(50.61,6.46) v1(51.63,7.48) v1(51.63,6.46) v1(53.47,66.88) v1(53.47,65.86) v1(54.48,66.88) v1(55.5,66.88) v1(55.5,65.86) v1(56.64,65.68) v1(57.66,65.68) v1(59.69,65.68) v1(60.71,65.68) v1(64.63,52.78) v1(64.63,51.77) v1(66.81,52.78) v1(66.81,51.77)
PCADR: length 4
  TOP w0.165: 30.64,26.16 30.64,25.17 v1(31.75,24.05) R23.2
  TOP w0.254: U5.69 30.64,26.15 30.64,26.16
  BOTTOM w0.165: R23.2 v1(31.75,24.05)
PCSCL: length 41.2
  TOP w0.165: v1(42.67,41.71) 42.88,41.91 44.73,41.91 51.87,49.05 55.93,49.05 60.53,44.45 R17.2 ; U5.22 33.04,40.99 33.04,40.06 v1(33.25,39.85)
  BOTTOM w0.165: v1(42.67,41.71) 42.11,41.15 34.2,41.15 33.25,40.2 v1(33.25,39.85) 32.7,39.3 R40.2
PCSDA: length 41.6
  TOP w0.165: v1(34.06,39.78) 33.44,40.4 33.44,41 33.44,41 U5.21 ; R18.2 60.91,43.18 55.52,48.56 52.4,48.56 45.28,41.45 v1(44.09,41.45)
  BOTTOM w0.165: R39.2 33.66,39.37 v1(34.06,39.78) 34.06,40.05 34.42,40.41 36.14,40.41 36.4,40.16 36.4,39.7 36.63,39.47 40.72,39.47 41.96,40.72 43.36,40.72 v1(44.09,41.45)
R0PWR5V: length 30
  TOP w0.165: R4.1 R5.2 24.97,60.27 24.43,59.74 23.39,59.74 22.96,59.31 22.96,54.28 22.28,53.59 22.28,48.31 24.92,45.67 v1(24.92,42.88) ; v1(27.48,41.76) 27.48,41.27 28.17,40.59 28.32,40.59 28.83,40.08 30,40.08 30.24,40.33 30.24,41.11 30.24,41.11 U5.29
  BOTTOM w0.165: v1(27.48,41.76) 26.04,41.76 v1(24.92,42.88)
R1PWR5V: length 2.8
  TOP w0.165: v1(32.31,39.88) 32.23,39.88 31.84,40.27 31.84,41.11 31.84,41.11 U5.25
  BOTTOM w0.165: R41.1 31.89,39.08 31.89,39.46 v1(32.31,39.88)
RX_CEC: length 134.3
  TOP w0.165: D3.1 27.18,44.97 R14.2 v1(28.89,48.46) ; R19.2 61.91,39.69 61.59,39.37 54.41,39.37 v1(52.63,37.59) ; J1.13 v1(21.5,63.97)
  BOTTOM w0.165: v1(28.89,48.46) 22.43,48.46 ; 22.43,48.46 20.85,50.04 20.85,61.24 21.5,61.89 v1(21.5,63.97) ; 22.43,48.46 18.54,44.58 18.54,17.55 21.62,14.48 51.51,14.48 52.63,15.6 v1(52.63,37.59)
RX_HPD0: length 31.4
  TOP w0.165: J1.19 24.5,64.08 24.77,63.82 27.98,63.82 29.73,62.06 R6.2 R7.2 30.91,58.85 v1(30.8,58.74) ; R13.2 26.17,42.88 D3.2 26.17,48.9 26.85,49.58 28.52,49.58 29.24,50.29 v1(29.24,51.99)
  BOTTOM w0.165: v1(30.8,58.74) 30.8,56.25 31.19,55.85 31.19,53.95 v1(29.24,51.99)
SATUS_INT: length 46
  TOP w0.165: v1(48.56,48.03) 49.99,49.45 56.36,49.45 60.73,45.09 67.15,45.09 67.63,44.6 J3.39 ; v1(34.61,37.19) 34.61,37.2 35.46,38.05 39.65,38.05 42.14,40.54 47.19,40.54 v1(48.56,41.91)
  BOTTOM w0.165: v1(48.56,41.91) v1(48.56,48.03) ; R38.1 v1(34.61,37.19)
SCDT_3DR_EVODD: length 3.3
  TOP w0.165: v1(44.78,38.33) 44.73,38.27 42.74,38.27
  TOP w0.254: U5.124 42.76,38.25 42.74,38.27
  BOTTOM w0.165: v1(44.78,38.33) 45.75,38.33 R35.2
SCDT_DR5: length 8.6
  TOP w0.165: R10.2 34.4,47.43 34.85,46.99 35.79,46.99 36.15,46.63 36.15,43.52 35.56,42.93 35.56,42.19 35.45,42.08 35.45,41.27
  TOP w0.254: 35.45,41.27 35.44,41.27 U5.16
SCDT_DR5_LED: length 1.5
  TOP w0.165: R10.1 D4.2
SCL_HDMI0_DDC_CI: length 38.6
  TOP w0.165: J1.15 v1(22.5,63.97) ; R15.2 30.16,52.16 27.91,54.41 25.68,54.41 25.07,53.8 25.07,52.13 U4.6 v1(25.08,50.65) 24.95,50.51 D2.2
  BOTTOM w0.165: R33.2 v1(25.08,50.65) 24.62,50.18 22.13,50.18 21.44,50.88 21.44,60.99 22.5,62.05 v1(22.5,63.97)
SDA_HDMI0_DDC_CI: length 38.7
  TOP w0.165: D2.1 23.95,50.51 v1(23.81,50.65) U4.5 23.88,52.18 23.88,53.49 25.3,54.91 28.3,54.91 30.76,52.45 30.76,46.13 31.11,45.77 R16.2 ; J1.16 23,64.25 v1(23.38,63.87)
  BOTTOM w0.165: R34.2 v1(23.81,50.65) 22.91,50.65 21.97,51.59 21.97,60.76 23.39,62.18 23.39,63.86 v1(23.38,63.87)
SPI1_CLK: length 64.8
  TOP w0.165: v1(62.49,20.36) 43.91,20.36 43,19.46 35.83,19.46 33.66,21.63 R24.1 ; J3.45 v1(62.48,47.6)
  BOTTOM w0.165: v1(62.48,47.6) 62.49,47.59 v1(62.49,20.36)
SPI1_CSZ_X: length 61.3
  TOP w0.165: v1(62.99,21.01) 43.74,21.01 42.65,19.91 36.33,19.91 34.61,21.63 R25.1 ; v1(62.99,45.57) 62.99,45.57 67.25,45.57 67.73,45.1 J3.40
  BOTTOM w0.165: v1(62.99,21.01) 62.99,21.01 v1(62.99,45.57)
SPI1_SIMO: length 59.7
  TOP w0.165: J3.41 67.73,45.6 67.3,46.04 v1(63.7,46.04) ; R26.1 35.56,21.63 36.68,20.51 42.48,20.51 43.4,21.43 61.03,21.43 61.39,21.79 v1(63.45,21.79)
  BOTTOM w0.165: v1(63.7,46.04) 63.7,44.65 63.45,44.4 v1(63.45,21.79)
SPI1_SOMI: length 2.4
  TOP w0.165: R12.1 66.95,46.6 J3.43
SPI_CLK: length 3.1
  TOP w0.165: 33.84,26.16 33.84,25.17 34.02,24.99 34.02,23.74 R24.2
  TOP w0.254: U5.77 33.84,26.16
SPI_DI: length 59.8
  TOP w0.165: R12.2 61.12,46.67 v1(61.11,46.66) ; U5.80 35.04,25.84 35.03,25.83 35.03,24.63 35.53,24.13 35.97,24.13 36.63,23.47 36.63,21.69 37.47,20.85 42.14,20.85 43.18,21.89 v1(60.68,21.89)
  BOTTOM w0.165: v1(61.11,46.66) 61.11,24.15 60.68,23.72 v1(60.68,21.89)
SPI_DO: length 3.3
  TOP w0.165: R26.2 34.71,24.23 34.71,25.28 34.65,25.34 34.65,26.16
  TOP w0.254: 34.65,26.16 34.64,26.15 U5.79
SPI_SS: length 3.1
  TOP w0.165: R25.2 34.36,23.63 34.36,25.14 34.24,25.25 34.24,26.16
  TOP w0.254: U5.78 34.24,26.15 34.24,26.16
SYSRSTN: length 3.6
  TOP w0.165: U5.15 35.84,41 35.83,40.99 35.83,39.83 v1(35.86,39.8)
  BOTTOM w0.165: v1(35.86,39.8) 35.86,39.59 R36.2 C39.2
TVCC33: length 6.1
  TOP w0.254: v1(43.92,37.52) 43.87,37.47 42.74,37.47 42.75,37.46 U5.122
  TOP w0.508: v1(43.92,37.52) 43.97,37.47 45.44,37.47 C75.1
  BOTTOM w0.381: C34.1 43.24,37.52 v1(43.92,37.52)
  BOTTOM w0.508: v1(43.92,37.52) 43.99,37.59 L14.1
TX0N: length 26.8
  TOP w0.102: U5.119 42.99,36.25 42.99,36.25 43.59,36.25 43.66,36.18 65.39,36.18 66.18,36.98 68.18,36.98 68.31,37.1 J3.24
TX0P: length 26.8
  TOP w0.102: J3.23 68.31,36.6 68.18,36.72 66.29,36.72 65.49,35.93 43.68,35.93 43.61,35.86 42.87,35.86 U5.118
TX1N: length 26.5
  TOP w0.102: J3.21 68.31,35.6 68.18,35.48 66.46,35.48 66.36,35.38 43.65,35.38 43.56,35.46 42.97,35.46 42.96,35.46 U5.117
TX1P: length 26.5
  TOP w0.102: U5.116 42.87,35.05 43.58,35.05 43.65,35.13 66.47,35.13 66.57,35.22 68.18,35.22 68.31,35.1 J3.20
TX2N: length 26.5
  TOP w0.102: J3.18 68.31,34.1 68.18,33.98 66.68,33.98 66.47,34.19 43.62,34.19 43.56,34.25 43,34.25 43,34.25 U5.114
TX2P: length 26.5
  TOP w0.102: J3.17 68.31,33.6 68.18,33.72 66.58,33.72 66.37,33.93 43.62,33.93 43.55,33.87 42.88,33.87 U5.113
TX3N: length 26.8
  TOP w0.102: U5.112 42.94,33.46 42.95,33.45 43.55,33.45 43.62,33.38 65.86,33.38 66.76,32.48 68.18,32.48 68.31,32.6 J3.15
TX3P: length 26.8
  TOP w0.102: J3.14 68.31,32.1 68.18,32.22 66.66,32.22 65.76,33.12 43.62,33.12 43.55,33.05 42.92,33.05 42.92,33.06 U5.111
TX4N: length 26.8
  TOP w0.102: U5.108 42.87,31.85 43.59,31.85 43.66,31.78 65.63,31.78 66.43,30.98 68.18,30.98 68.31,31.1 J3.12
TX4P: length 26.8
  TOP w0.102: U5.107 42.93,31.46 42.93,31.46 43.58,31.46 43.65,31.53 65.52,31.53 66.33,30.72 68.18,30.72 68.31,30.6 J3.11
TX5N: length 27.1
  TOP w0.102: J3.9 68.31,29.6 68.18,29.48 66.34,29.48 64.83,30.99 43.67,30.99 43.6,31.06 42.91,31.06 42.9,31.06 U5.106
TX5P: length 27.1
  TOP w0.102: J3.8 68.31,29.1 68.18,29.22 66.23,29.22 64.72,30.73 43.67,30.73 43.58,30.65 42.88,30.65 U5.105
TX6N: length 27.2
  TOP w0.102: U5.103 42.96,29.85 42.96,29.86 43.56,29.86 43.65,29.76 64.52,29.76 66.31,27.98 68.18,27.98 68.31,28.1 J3.6
TX6P: length 27.2
  TOP w0.102: U5.102 42.97,29.46 42.98,29.46 43.57,29.46 43.61,29.51 64.42,29.51 66.2,27.72 68.18,27.72 68.31,27.6 J3.5
TX7N: length 27.5
  TOP w0.102: J3.3 68.31,26.6 68.18,26.48 66.33,26.48 63.83,28.98 43.68,28.98 43.59,29.08 42.98,29.08 42.95,29.06 U5.101
TX7P: length 27.5
  TOP w0.102: J3.2 68.31,26.1 68.18,26.22 66.23,26.22 63.72,28.73 43.66,28.73 43.59,28.66 42.98,28.66 42.98,28.66 U5.100
VBO_AVDD10: length 4.6
  TOP w0.254: U5.115 43.08,34.65 43.09,34.67 v1(43.89,34.67) ; v1(43.89,30.2) 43.83,30.26 42.98,30.26 42.97,30.25 U5.104
  TOP w0.381: C15.1 v1(45.8,32.38)
  BOTTOM w0.381: v1(43.89,34.67) 43.23,34.67 C48.1 ; C59.1 43.33,30.2 v1(43.89,30.2)
VBO_PVCC10: length 9.9
  TOP w0.254: v1(41.48,36.58) 41.56,36.66 42.86,36.66 U5.120 ; v1(43.89,32.23) 43.85,32.27 42.88,32.27 U5.109 ; v1(43.92,26.95) 43.92,27.01 43.47,27.45 43.01,27.45 43.01,27.46 U5.97
  TOP w0.381: v1(43.92,26.95) 43.92,25.81 44.44,25.29 C21.1 L10.1
  BOTTOM w0.381: v1(43.89,32.23) 43.45,32.23 C49.1 ; C65.1 43.81,26.85 v1(43.92,26.95) ; v1(41.48,36.58) 41.61,36.7 42.21,36.7 C50.1
VBO_PVCC33: length 5.3
  TOP w0.254: v1(43.96,27.86) 43,27.86 43,27.85 U5.98
  TOP w0.381: v1(43.96,27.86) 43.99,27.83 C20.1 L9.1
  BOTTOM w0.381: v1(43.96,27.86) 43.87,27.76 42.25,27.76 C60.1
VX1_PROJ_ON: length 18.7
  TOP w0.165: TP6.1 61.28,40.01 61.59,40.32 67.31,40.32 67.53,40.1 J3.30
XTALIN: length 10.2
  TOP w0.165: Y1.3 31.35,19.17 C23.2 31.43,20.21 30.84,20.8 30.84,22.71 30.05,23.5 R22.1 29.35,23.56 29.35,24.13 29.06,24.42 29.06,24.88 29.43,25.26 29.43,26.16
  TOP w0.254: U5.66 29.44,26.15 29.43,26.16
XTALOUT: length 6.9
  TOP w0.165: C22.2 27.96,21.48 Y1.1 27.97,23.09 R22.2 28.37,24.66 29.04,25.32 29.04,26.16
  TOP w0.254: U5.65 29.04,26.15 29.04,26.16

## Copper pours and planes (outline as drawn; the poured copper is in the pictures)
AVDD10 on TOP: 21.16,30.1 23.19,30.1 23.6,30.51 23.6,30.68 23.77,30.86 25.37,30.86 25.68,30.56 25.68,30.12 25.93,29.87 26.75,29.87 26.95,30.07 26.95,32.82 26.72,33.05 25.76,33.05 25.6,32.89 25.6,32.26 25.63,32.23 25.63,31.75 25.35,31.47 23.6,31.47 23.06,32 21.64,32 21.01,31.37 21.01,30.25
AVDD10 on LY3: 28.32,39.07 29.92,39.07 30.61,38.38 30.61,29.97 30.12,29.49 26.31,29.49 25.78,30.02 25.78,32.59 26.29,33.1 28.17,33.1 28.17,35.66 27.99,35.84 27.99,38.73
GND on TOP (solid shape): 50.61,64.2 47.82,64.2 47.82,68.52 50.61,68.52
GND on TOP (solid shape): 57.28,4.83 54.48,4.83 54.48,9.14 57.28,9.14
GND on TOP: 47.55,70.43 49.89,70.43 50.42,69.9 50.42,69.55 50.39,69.52 50.39,69.04 50.62,68.81 50.62,65.02 50.83,64.82 61.75,64.82 62.56,64.01 62.56,59.13 62.53,59.11 54.61,59.11 54.58,59.13 54.58,61.44 54.61,61.47 54.61,61.82 53.64,62.79 48.18,62.79 47.78,63.2 47.78,68.81 47.55,69.04
GND on TOP: 57.54,2.91 55.21,2.91 54.67,3.44 54.67,3.8 54.7,3.82 54.7,4.31 54.47,4.53 54.47,8.32 54.27,8.52 43.35,8.52 42.53,9.33 42.53,14.21 42.56,14.24 50.48,14.24 50.51,14.21 50.51,11.9 50.48,11.87 50.48,11.52 51.45,10.55 56.91,10.55 57.32,10.15 57.32,4.53 57.54,4.31
GND on LY2: 0.76,0.76 0.76,75.44 75.44,75.44 75.44,0.76
GND on LY3: 0.76,0.76 0.76,75.44 75.44,75.44 75.44,0.76 ; 3 cut-outs
P5V on TOP: 69.93,48.97 65.25,48.97 65.07,49.15 65.07,50.7 65.13,50.75 69.82,50.75 69.93,50.65
VCC33 on TOP: 26.87,38.23 26.87,39.47 26.31,40.03 23.47,40.03 23.24,39.8 23.24,38.4 23.6,38.05 26.7,38.05
IVDD10 on LY3: 32.08,44.81 42.98,44.81 50.16,37.62 50.16,25.96 49.86,25.65 48.46,25.65 48.23,25.88 48.23,26.8 47.57,27.46 46.28,27.46 45.62,26.8 45.62,24.03 44.5,22.91 31.24,22.91 30.07,24.08 30.07,42.8
OVDD33 on BOTTOM: 28.73,45.09 45.14,45.09 45.87,44.35 45.87,36.14 45.52,35.79 42.55,35.79 42.55,21.91 41.52,20.88 29.26,20.88 27.74,22.4 27.74,44.09 ; 2 cut-outs
P1P0V on TOP: 54.98,11.14 51.85,11.14 51.12,11.87 51.12,14.54 50.71,14.95 42.63,14.95 42.58,15 42.58,18.66 43.24,19.32 54.85,19.32 55,19.16 55,11.16
P1P0V on BOTTOM: 20.35,33.07 24.33,33.07 24.87,32.54 24.87,29.72 24.84,29.69 24.84,24.26 28.7,20.4 44.27,20.4 45.9,22.02 45.9,25.3 46.18,25.58 51.31,25.58 51.92,24.97 51.92,15.98 51.18,15.24 22.99,15.24 19.79,18.44 19.79,32.51
P1P0V_SW on TOP: 59.4,8.57 59.4,9.28 60.62,10.5 60.62,19.19 60.54,19.27 58.23,19.27 58,19.04 58,10.6 57.75,10.35 57.75,8.62 57.8,8.57
P3P3V on TOP: 50.11,62.2 53.24,62.2 53.98,61.47 53.98,58.8 54.38,58.39 62.46,58.39 62.51,58.34 62.51,54.69 61.85,54.03 50.24,54.03 50.09,54.18 50.09,62.18
P3P3V on LY3: 23.77,44.4 24.77,45.39 34.67,45.39 38.28,49 57.43,49 62.41,53.98 62.41,56.18 62,56.59 53.7,56.59 49.91,52.81 38.46,52.81 33.3,47.65 23.24,47.65 20.47,44.88 20.47,24.77 25.45,19.79 45.06,19.79 47.83,22.56 47.83,26.72 47.35,27.2 46.38,27.2 45.82,26.64 45.82,24 43.74,21.92 30.1,21.92 23.77,28.24
P3P3V_SW on TOP: 45.69,64.77 45.69,64.06 44.48,62.84 44.48,54.15 44.55,54.08 46.86,54.08 47.09,54.31 47.09,62.74 47.35,62.99 47.35,64.72 47.29,64.77
P5P0V on TOP: 54.01,6.03 43.47,6.03 43.27,6.24 43.27,7.45 43.8,7.99 53.91,7.99 54.01,7.89
P5P0V on TOP: 51.08,67.31 61.62,67.31 61.82,67.11 61.82,65.89 61.29,65.35 51.18,65.35 51.08,65.46
P5P0V on TOP: 66.95,53.04 64.49,53.04 64.34,52.88 64.34,51.66 64.52,51.49 66.93,51.49 67.11,51.66 67.11,52.88
P5P0V on BOTTOM: 54.08,61.44 61.49,61.44 64.14,58.8 64.14,9.04 63.65,8.56 43.71,8.56 43.15,8 43.15,1.32 43.64,0.84 69.09,0.84 72.57,4.32 72.57,69.67 53.8,69.67 53.01,68.88 53.01,62.51
VBO_AVDD10 on BOTTOM: 46.89,34.98 46.89,26.09 46.79,25.98 44.91,25.98 44.58,26.31 44.58,29.18 44.02,29.74 42.93,29.74 42.82,29.84 42.82,31.17 43.15,31.5 44.22,31.5 44.42,31.7 44.42,33.68 44.02,34.09 43.03,34.09 42.82,34.29 42.82,35.1 42.95,35.23 46.63,35.23
VBO_PVCC10 on LY3: 43.41,26.57 44.15,26.57 44.81,27.23 44.81,34.59 42.29,37.11 41.12,37.11 40.84,36.83 40.84,35.43 42.75,33.53 42.75,27.23

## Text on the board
BOTTOM: LAYER 4 - BOTTOM | 4
Board Geometry/Soldermask Bottom: SOLDERMASK BOTTOM | 6
Ref Des/Silkscreen Bottom: SILKSCREEN BOTTOM | 8
TOP: LAYER 1 - TOP | 1
Board Geometry/Soldermask Top: SOLDERMASK TOP | 5
Ref Des/Silkscreen Top: R | TEXAS INSTRUMENTS | DLP  PRODUCTS | FRONT-END BOARD | DLP064A | DLPC7540EVM | SILKSCREEN TOP | 7
LY2: LAYER 2 - GND PLANE | 2
LY3: LAYER 3 - PLANE | 3
DIMENSION: SOLDERPASTE TOP | 9
User.6: SOLDERPASTE BOTTOM | 10
User.7: LINE WIDTH (MILS) | LINE WIDTH/SPACING (MILS) | PCB MUST BEAR THE UL94V-0 UL REGISTERED MATERIAL ID NUMBER. | ACTUAL FABRICATION DATA MUST BE REVIEWED AND APPROVED. | 4. ALL BOARDS MUST MEET OR EXCEED UL94V-0 REQUIREMENTS. | 5. MINIMUM COPPER WALL THICKNESS OF PLATED-THRU | HOLES TO BE .001 INCH, WITH A MINIMUM | ANNULAR RING OF .002 INCH. | 6. OVERALL BOARD THICKNESS TO BE .093 +/- 10% | AND APPLIES AFTER ALL LAMINATION AND PLATING | PROCESSES, MEASURED FROM COPPER TO COPPER. | 7. MAX. WARP & TWIST TO BE .0075 INCHES PER INCH. | 8. ANY DESCREPENCY BETWEEN FABRICATION PRINT AND THE | 3. BOARD MATERIAL SHALL BE ISOLA FR408HR OR | EQUIVALENT, RoHS AND REACH COMPLIANT AND LEAD FREE | ASSEMBLY CAPABLE.  BOARD MATERIAL SHALL | MEET OR EXCEED IPC-4101B. RoHS AND REACH CERTIFICATE OF | CONFORMANCE SHALL BE DELIVERED WITH EACH LOT. | FAB NOTES: | 2. THE PWB SHALL BE FABRICATED TO IPC-6012, | CLASS 2 AND WORKMANSHIP SHALL CONFORM TO | IPC-A-600, CLASS 2. CURRENT REVISIONS. | 1. ALL DIMENSIONS ARE IN INCHES UNLESS | OTHERWISE NOTED.  ALL BOARD | OUTLINE DIMENSION TOLERANCES ARE +/- .010". | EXCEPT AS NOTED BELOW, SOLDERMASK ARTWORK IS SIZED 1:1 WITH SOLDER PAD FEATURES. | VENDOR TO ADJUST FOR THEIR PROCESSES.  MUST MAINTAIN WEB | OF SOLDERMASK BETWEEN ALL EXPOSED PLATED SURFACES. | NICKEL 100 MICROINCHES THK MIN, GOLD 2-6 MICROINCHES THK. | PREPREG | CORE | 2 | 3 | 4 | LAYER | 1 | SOLDERMASK | SILKSCREEN | SIGNAL | PLANE | DEFINITION | PREPREG/CORE | THICKNESS | (MILS) | 4.2 | 78 | FINISHED | 1/2 OZ | 1 OZ | Cu WT. | 50 OHMS | 6.5 | IMPEDANCE REQUIREMENTS | 100 OHMS DIFFERENTIAL | 4/6 | DRILL CHART FAB DWG | 11 | + | 10% | 0.093 | - | LAYER STACKUP
User.15: DLPC7540EVM FRONT END BOARD | A
